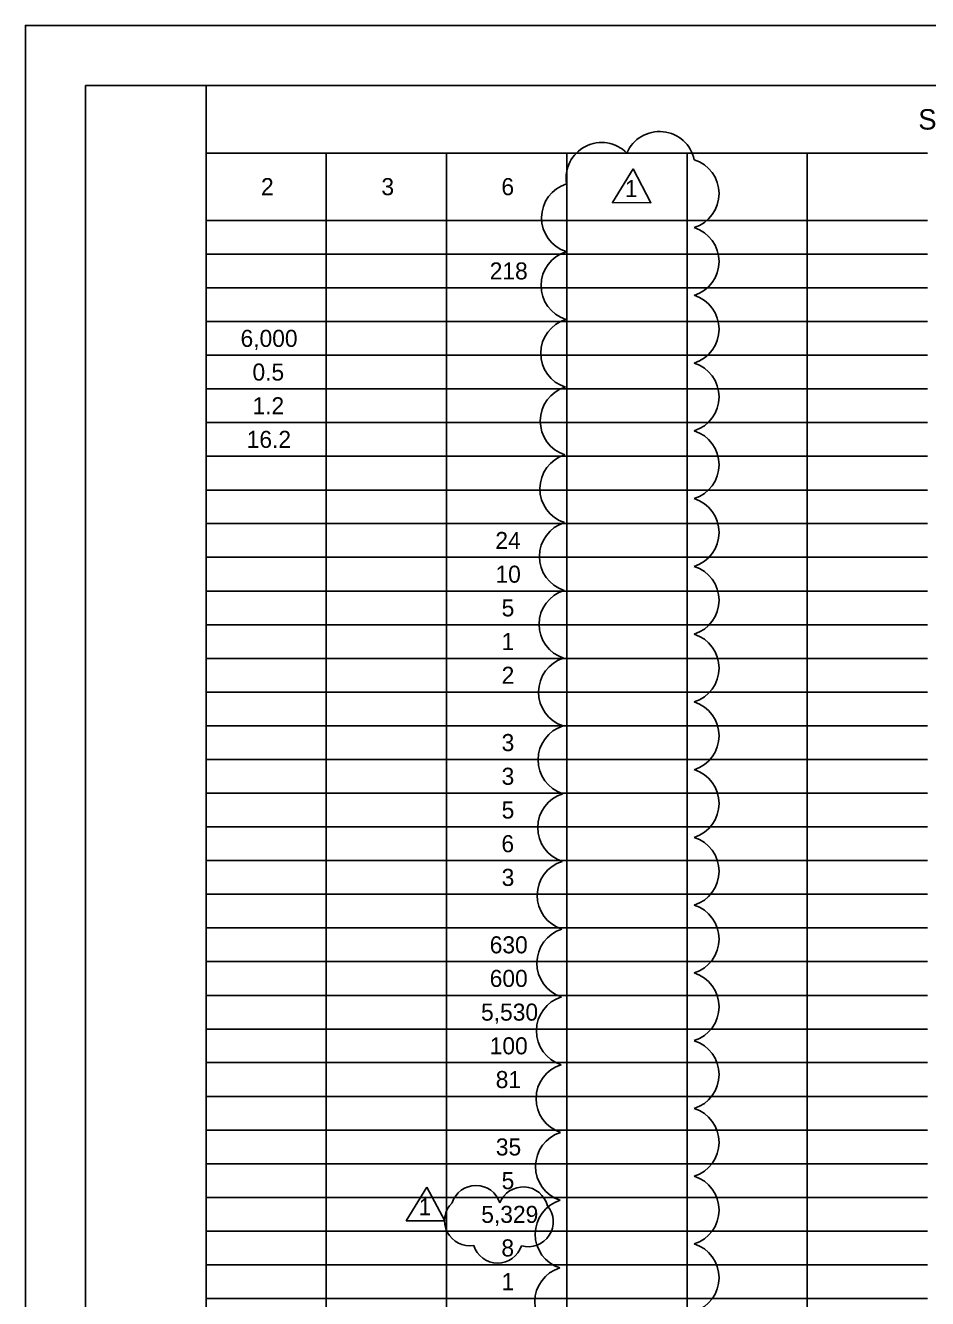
# Model space of a CAD drawing. Extents: x 0 to 34, y 0 to 22.
# Drawn here: x 0 to 7.49, y 11.42 to 22 of the extents above; entities that cross this region are included whole.
import ezdxf

# ---------------------------------------------------------------- set-up
doc = ezdxf.new("R2010")
doc.units = 0
for name, color, linetype in [('Default', 7, 'Continuous'), ('SH_Border', 7, 'Continuous'), ('SH_Cut_Line', 7, 'Continuous'), ('SH_Text', 7, 'Continuous')]:
    doc.layers.add(name, color=color, linetype=linetype)

msp = doc.modelspace()

# ---------------------------------------------------------------- linework, layer by layer
at = {"layer": 'Default'}
for points in [[(5.048, 20.808), (4.877, 20.529), (5.197, 20.527)], [(3.335, 12.35), (3.164, 12.071), (3.484, 12.069)]]:
    msp.add_lwpolyline(points, close=True, dxfattribs=at)
for centre, radius, start, end in [((5.268, 20.824), 0.295, 11.7951, 156.7951), ((4.787, 20.733), 0.295, 44.5745, 189.5745), ((5.468, 20.603), 0.295, 287.5295, 72.5295), ((4.583, 20.402), 0.295, 107.1401, 252.1401), ((5.468, 20.039), 0.295, 287.5, 72.5), ((4.579, 19.839), 0.295, 107.1401, 252.1401), ((5.468, 19.477), 0.295, 287.5, 72.5), ((4.576, 19.276), 0.295, 107.1401, 252.1401), ((5.468, 18.914), 0.295, 287.5, 72.5), ((4.572, 18.714), 0.295, 107.1401, 252.1401), ((5.468, 18.351), 0.295, 287.5, 72.5), ((4.569, 18.151), 0.295, 107.1401, 252.1401), ((5.468, 17.788), 0.295, 287.5, 72.5), ((4.565, 17.588), 0.295, 107.1401, 252.1401), ((5.468, 17.225), 0.295, 287.5, 72.5), ((4.562, 17.025), 0.295, 107.1401, 252.1401), ((5.468, 16.662), 0.295, 287.5, 72.5), ((4.558, 16.462), 0.295, 107.1401, 252.1401), ((5.468, 16.099), 0.295, 287.5, 72.5), ((4.554, 15.899), 0.295, 107.1401, 252.1401), ((5.468, 15.537), 0.295, 287.5, 72.5), ((4.551, 15.336), 0.295, 107.1401, 252.1401), ((5.468, 14.974), 0.295, 287.5, 72.5), ((4.547, 14.774), 0.295, 107.1401, 252.1401), ((5.468, 14.411), 0.295, 287.5, 72.5), ((4.544, 14.211), 0.295, 107.1401, 252.1401), ((5.468, 13.848), 0.295, 287.5, 72.5), ((4.54, 13.648), 0.295, 107.1401, 252.1401), ((5.468, 13.285), 0.295, 287.5, 72.5), ((4.537, 13.085), 0.295, 107.1401, 252.1401), ((5.468, 12.722), 0.295, 287.5, 72.5), ((4.533, 12.522), 0.295, 107.1401, 252.1401), ((5.468, 12.159), 0.295, 287.5, 72.5), ((3.743, 12.156), 0.208, 17.5, 162.5), ((4.135, 12.144), 0.208, 14.1039, 159.1039), ((3.69, 12.071), 0.208, 134.5743, 279.5743), ((4.177, 12.063), 0.208, 254.4905, 39.4905), ((4.53, 11.959), 0.295, 107.1401, 252.1401), ((3.923, 11.927), 0.208, 197.0681, 342.0681), ((5.468, 11.597), 0.295, 287.5, 72.5), ((4.526, 11.397), 0.295, 107.1401, 252.1401)]:
    msp.add_arc(centre, radius, start, end, dxfattribs=at)
at = {"layer": 'SH_Border'}
for points in [[(0.5, 21.5), (1.5, 21.5), (1.5, 0.5), (0.5, 0.5)], [(1.5, 21.5), (33.5, 21.5), (33.5, 0.5), (1.5, 0.5)]]:
    msp.add_lwpolyline(points, close=True, dxfattribs=at)
at = {"layer": 'SH_Cut_Line'}
msp.add_lwpolyline([(0, 0), (34, 0), (34, 22), (0, 22)], close=True, dxfattribs=at)
at = {"layer": 'SH_Text'}
for p, q in [((1.5, 21.5), (2.499, 21.5)), ((1.5, 21.5), (1.5, 21.22)), ((2.499, 21.5), (4.497, 21.5)), ((4.497, 21.5), (5.497, 21.5)), ((5.497, 21.5), (6.496, 21.5)), ((6.496, 21.5), (7.495, 21.5)), ((1.5, 21.22), (1.5, 20.94)), ((1.5, 20.94), (2.499, 20.94)), ((1.5, 20.94), (1.5, 20.66)), ((2.499, 20.94), (4.497, 20.94)), ((2.499, 20.94), (2.499, 20.66)), ((3.498, 20.94), (3.498, 20.66)), ((4.497, 20.94), (5.497, 20.94)), ((4.497, 20.94), (4.497, 20.66)), ((5.497, 20.94), (6.496, 20.94)), ((5.497, 20.94), (5.497, 20.66)), ((6.496, 20.94), (7.495, 20.94)), ((6.496, 20.94), (6.496, 20.66)), ((1.5, 20.66), (1.5, 20.38)), ((2.499, 20.66), (2.499, 20.38)), ((3.498, 20.66), (3.498, 20.38)), ((4.497, 20.66), (4.497, 20.38)), ((5.497, 20.66), (5.497, 20.38)), ((6.496, 20.66), (6.496, 20.38)), ((1.5, 20.38), (2.499, 20.38)), ((1.5, 20.38), (1.5, 20.101)), ((2.499, 20.38), (4.497, 20.38)), ((2.499, 20.38), (2.499, 20.101)), ((3.498, 20.38), (3.498, 20.101)), ((4.497, 20.38), (5.497, 20.38)), ((4.497, 20.38), (4.497, 20.101)), ((5.497, 20.38), (6.496, 20.38)), ((5.497, 20.38), (5.497, 20.101)), ((6.496, 20.38), (7.495, 20.38)), ((6.496, 20.38), (6.496, 20.101)), ((1.5, 20.101), (2.499, 20.101)), ((1.5, 20.101), (1.5, 18.701)), ((2.499, 20.101), (4.497, 20.101)), ((2.499, 20.101), (2.499, 18.701)), ((3.498, 20.101), (3.498, 18.701)), ((4.497, 20.101), (5.497, 20.101)), ((4.497, 20.101), (4.497, 18.701)), ((5.497, 20.101), (6.496, 20.101)), ((5.497, 20.101), (5.497, 18.701)), ((6.496, 20.101), (7.495, 20.101)), ((6.496, 20.101), (6.496, 18.701)), ((1.5, 19.821), (2.499, 19.821)), ((2.499, 19.821), (4.497, 19.821)), ((4.497, 19.821), (5.497, 19.821)), ((5.497, 19.821), (6.496, 19.821)), ((6.496, 19.821), (7.495, 19.821)), ((1.5, 19.541), (2.499, 19.541)), ((2.499, 19.541), (4.497, 19.541)), ((4.497, 19.541), (5.497, 19.541)), ((5.497, 19.541), (6.496, 19.541)), ((6.496, 19.541), (7.495, 19.541)), ((1.5, 19.261), (2.499, 19.261)), ((2.499, 19.261), (4.497, 19.261)), ((4.497, 19.261), (5.497, 19.261)), ((5.497, 19.261), (6.496, 19.261)), ((6.496, 19.261), (7.495, 19.261)), ((1.5, 18.981), (2.499, 18.981)), ((2.499, 18.981), (4.497, 18.981)), ((4.497, 18.981), (5.497, 18.981)), ((5.497, 18.981), (6.496, 18.981)), ((6.496, 18.981), (7.495, 18.981)), ((1.5, 18.701), (2.499, 18.701)), ((1.5, 18.701), (1.5, 18.141)), ((2.499, 18.701), (4.497, 18.701)), ((2.499, 18.701), (2.499, 18.141)), ((3.498, 18.701), (3.498, 18.141)), ((4.497, 18.701), (5.497, 18.701)), ((4.497, 18.701), (4.497, 18.141)), ((5.497, 18.701), (6.496, 18.701)), ((5.497, 18.701), (5.497, 18.141)), ((6.496, 18.701), (7.495, 18.701)), ((6.496, 18.701), (6.496, 18.141)), ((1.5, 18.421), (2.499, 18.421)), ((2.499, 18.421), (4.497, 18.421)), ((4.497, 18.421), (5.497, 18.421)), ((5.497, 18.421), (6.496, 18.421)), ((6.496, 18.421), (7.495, 18.421)), ((1.5, 18.141), (2.499, 18.141)), ((1.5, 18.141), (1.5, 17.862)), ((2.499, 18.141), (4.497, 18.141)), ((2.499, 18.141), (2.499, 17.862)), ((3.498, 18.141), (3.498, 17.862)), ((4.497, 18.141), (5.497, 18.141)), ((4.497, 18.141), (4.497, 17.862)), ((5.497, 18.141), (6.496, 18.141)), ((5.497, 18.141), (5.497, 17.862)), ((6.496, 18.141), (7.495, 18.141)), ((6.496, 18.141), (6.496, 17.862)), ((1.5, 17.862), (2.499, 17.862)), ((1.5, 17.862), (1.5, 17.582)), ((2.499, 17.862), (4.497, 17.862)), ((2.499, 17.862), (2.499, 17.582)), ((3.498, 17.862), (3.498, 17.582)), ((4.497, 17.862), (5.497, 17.862)), ((4.497, 17.862), (4.497, 17.582)), ((5.497, 17.862), (6.496, 17.862)), ((5.497, 17.862), (5.497, 17.582)), ((6.496, 17.862), (7.495, 17.862)), ((6.496, 17.862), (6.496, 17.582)), ((1.5, 17.582), (2.499, 17.582)), ((1.5, 17.582), (1.5, 17.302)), ((2.499, 17.582), (4.497, 17.582)), ((2.499, 17.582), (2.499, 17.302)), ((3.498, 17.582), (3.498, 17.302)), ((4.497, 17.582), (5.497, 17.582)), ((4.497, 17.582), (4.497, 17.302)), ((5.497, 17.582), (6.496, 17.582)), ((5.497, 17.582), (5.497, 17.302)), ((6.496, 17.582), (7.495, 17.582)), ((6.496, 17.582), (6.496, 17.302)), ((1.5, 17.302), (2.499, 17.302)), ((1.5, 17.302), (1.5, 17.022)), ((2.499, 17.302), (4.497, 17.302)), ((2.499, 17.302), (2.499, 17.022)), ((3.498, 17.302), (3.498, 17.022)), ((4.497, 17.302), (5.497, 17.302)), ((4.497, 17.302), (4.497, 17.022)), ((5.497, 17.302), (6.496, 17.302)), ((5.497, 17.302), (5.497, 17.022)), ((6.496, 17.302), (7.495, 17.302)), ((6.496, 17.302), (6.496, 17.022)), ((1.5, 17.022), (2.499, 17.022)), ((1.5, 17.022), (1.5, 16.742)), ((2.499, 17.022), (4.497, 17.022)), ((2.499, 17.022), (2.499, 16.742)), ((3.498, 17.022), (3.498, 16.742)), ((4.497, 17.022), (5.497, 17.022)), ((4.497, 17.022), (4.497, 16.742)), ((5.497, 17.022), (6.496, 17.022)), ((5.497, 17.022), (5.497, 16.742)), ((6.496, 17.022), (7.495, 17.022)), ((6.496, 17.022), (6.496, 16.742)), ((1.5, 16.742), (2.499, 16.742)), ((1.5, 16.742), (1.5, 16.182)), ((2.499, 16.742), (4.497, 16.742)), ((2.499, 16.742), (2.499, 16.182)), ((3.498, 16.742), (3.498, 16.182)), ((4.497, 16.742), (5.497, 16.742)), ((4.497, 16.742), (4.497, 16.182)), ((5.497, 16.742), (6.496, 16.742)), ((5.497, 16.742), (5.497, 16.182)), ((6.496, 16.742), (7.495, 16.742)), ((6.496, 16.742), (6.496, 16.182)), ((1.5, 16.462), (2.499, 16.462)), ((2.499, 16.462), (4.497, 16.462)), ((4.497, 16.462), (5.497, 16.462)), ((5.497, 16.462), (6.496, 16.462)), ((6.496, 16.462), (7.495, 16.462)), ((1.5, 16.182), (2.499, 16.182)), ((1.5, 16.182), (1.5, 15.902)), ((2.499, 16.182), (4.497, 16.182)), ((2.499, 16.182), (2.499, 15.902)), ((3.498, 16.182), (3.498, 15.902)), ((4.497, 16.182), (5.497, 16.182)), ((4.497, 16.182), (4.497, 15.902)), ((5.497, 16.182), (6.496, 16.182)), ((5.497, 16.182), (5.497, 15.902)), ((6.496, 16.182), (7.495, 16.182)), ((6.496, 16.182), (6.496, 15.902)), ((1.5, 15.902), (2.499, 15.902)), ((1.5, 15.902), (1.5, 15.623)), ((2.499, 15.902), (4.497, 15.902)), ((2.499, 15.902), (2.499, 15.623)), ((3.498, 15.902), (3.498, 15.623)), ((4.497, 15.902), (5.497, 15.902)), ((4.497, 15.902), (4.497, 15.623)), ((5.497, 15.902), (6.496, 15.902)), ((5.497, 15.902), (5.497, 15.623)), ((6.496, 15.902), (7.495, 15.902)), ((6.496, 15.902), (6.496, 15.623)), ((1.5, 15.623), (2.499, 15.623)), ((1.5, 15.623), (1.5, 15.343)), ((2.499, 15.623), (4.497, 15.623)), ((2.499, 15.623), (2.499, 15.343)), ((3.498, 15.623), (3.498, 15.343)), ((4.497, 15.623), (5.497, 15.623)), ((4.497, 15.623), (4.497, 15.343)), ((5.497, 15.623), (6.496, 15.623)), ((5.497, 15.623), (5.497, 15.343)), ((6.496, 15.623), (7.495, 15.623)), ((6.496, 15.623), (6.496, 15.343)), ((1.5, 15.343), (2.499, 15.343)), ((1.5, 15.343), (1.5, 14.783)), ((2.499, 15.343), (4.497, 15.343)), ((2.499, 15.343), (2.499, 14.783)), ((3.498, 15.343), (3.498, 14.783)), ((4.497, 15.343), (5.497, 15.343)), ((4.497, 15.343), (4.497, 14.783)), ((5.497, 15.343), (6.496, 15.343)), ((5.497, 15.343), (5.497, 14.783)), ((6.496, 15.343), (7.495, 15.343)), ((6.496, 15.343), (6.496, 14.783)), ((1.5, 15.063), (2.499, 15.063)), ((2.499, 15.063), (4.497, 15.063)), ((4.497, 15.063), (5.497, 15.063)), ((5.497, 15.063), (6.496, 15.063)), ((6.496, 15.063), (7.495, 15.063)), ((1.5, 14.783), (2.499, 14.783)), ((1.5, 14.783), (1.5, 14.503)), ((2.499, 14.783), (4.497, 14.783)), ((2.499, 14.783), (2.499, 14.503)), ((3.498, 14.783), (3.498, 14.503)), ((4.497, 14.783), (5.497, 14.783)), ((4.497, 14.783), (4.497, 14.503)), ((5.497, 14.783), (6.496, 14.783)), ((5.497, 14.783), (5.497, 14.503)), ((6.496, 14.783), (7.495, 14.783)), ((6.496, 14.783), (6.496, 14.503)), ((1.5, 14.503), (2.499, 14.503)), ((1.5, 14.503), (1.5, 14.223)), ((2.499, 14.503), (4.497, 14.503)), ((2.499, 14.503), (2.499, 14.223)), ((3.498, 14.503), (3.498, 14.223)), ((4.497, 14.503), (5.497, 14.503)), ((4.497, 14.503), (4.497, 14.223)), ((5.497, 14.503), (6.496, 14.503)), ((5.497, 14.503), (5.497, 14.223)), ((6.496, 14.503), (7.495, 14.503)), ((6.496, 14.503), (6.496, 14.223)), ((1.5, 14.223), (2.499, 14.223)), ((1.5, 14.223), (1.5, 13.943)), ((2.499, 14.223), (4.497, 14.223)), ((2.499, 14.223), (2.499, 13.943)), ((3.498, 14.223), (3.498, 13.943)), ((4.497, 14.223), (5.497, 14.223)), ((4.497, 14.223), (4.497, 13.943)), ((5.497, 14.223), (6.496, 14.223)), ((5.497, 14.223), (5.497, 13.943)), ((6.496, 14.223), (7.495, 14.223)), ((6.496, 14.223), (6.496, 13.943)), ((1.5, 13.943), (2.499, 13.943)), ((1.5, 13.943), (1.5, 11.704)), ((2.499, 13.943), (4.497, 13.943)), ((2.499, 13.943), (2.499, 11.704)), ((3.498, 13.943), (3.498, 11.704)), ((4.497, 13.943), (5.497, 13.943)), ((4.497, 13.943), (4.497, 11.704)), ((5.497, 13.943), (6.496, 13.943)), ((5.497, 13.943), (5.497, 11.704)), ((6.496, 13.943), (7.495, 13.943)), ((6.496, 13.943), (6.496, 11.704)), ((1.5, 13.663), (2.499, 13.663)), ((2.499, 13.663), (4.497, 13.663)), ((4.497, 13.663), (5.497, 13.663)), ((5.497, 13.663), (6.496, 13.663)), ((6.496, 13.663), (7.495, 13.663)), ((1.5, 13.384), (2.499, 13.384)), ((2.499, 13.384), (4.497, 13.384)), ((4.497, 13.384), (5.497, 13.384)), ((5.497, 13.384), (6.496, 13.384)), ((6.496, 13.384), (7.495, 13.384)), ((1.5, 13.104), (2.499, 13.104)), ((2.499, 13.104), (4.497, 13.104)), ((4.497, 13.104), (5.497, 13.104)), ((5.497, 13.104), (6.496, 13.104)), ((6.496, 13.104), (7.495, 13.104)), ((1.5, 12.824), (2.499, 12.824)), ((2.499, 12.824), (4.497, 12.824)), ((4.497, 12.824), (5.497, 12.824)), ((5.497, 12.824), (6.496, 12.824)), ((6.496, 12.824), (7.495, 12.824)), ((1.5, 12.544), (2.499, 12.544)), ((2.499, 12.544), (4.497, 12.544)), ((4.497, 12.544), (5.497, 12.544)), ((5.497, 12.544), (6.496, 12.544)), ((6.496, 12.544), (7.495, 12.544)), ((1.5, 12.264), (2.499, 12.264)), ((2.499, 12.264), (4.497, 12.264)), ((4.497, 12.264), (5.497, 12.264)), ((5.497, 12.264), (6.496, 12.264)), ((6.496, 12.264), (7.495, 12.264)), ((1.5, 11.984), (2.499, 11.984)), ((2.499, 11.984), (4.497, 11.984)), ((4.497, 11.984), (5.497, 11.984)), ((5.497, 11.984), (6.496, 11.984)), ((6.496, 11.984), (7.495, 11.984)), ((1.5, 11.704), (2.499, 11.704)), ((1.5, 11.704), (1.5, 11.424)), ((2.499, 11.704), (4.497, 11.704)), ((2.499, 11.704), (2.499, 11.424)), ((3.498, 11.704), (3.498, 11.424)), ((4.497, 11.704), (5.497, 11.704)), ((4.497, 11.704), (4.497, 11.424)), ((5.497, 11.704), (6.496, 11.704)), ((5.497, 11.704), (5.497, 11.424)), ((6.496, 11.704), (7.495, 11.704)), ((6.496, 11.704), (6.496, 11.424)), ((1.5, 11.424), (2.499, 11.424)), ((1.5, 11.424), (1.5, 10.305)), ((2.499, 11.424), (4.497, 11.424)), ((2.499, 11.424), (2.499, 10.305)), ((3.498, 11.424), (3.498, 10.305)), ((4.497, 11.424), (5.497, 11.424)), ((4.497, 11.424), (4.497, 10.305)), ((5.497, 11.424), (6.496, 11.424)), ((5.497, 11.424), (5.497, 10.305)), ((6.496, 11.424), (7.495, 11.424)), ((6.496, 11.424), (6.496, 10.305))]:
    msp.add_line(p, q, dxfattribs=at)

# ---------------------------------------------------------------- texts
at = {"layer": 'Default'}
for p in [(4.98, 20.575), (3.267, 12.117)]:
    msp.add_text('1', height=0.14, dxfattribs=at).set_placement(p)
at = {"layer": 'SH_Text'}
for s, height, p in [('SHEET NUM.', 0.1699, (7.418, 21.135)), ('2', 0.142, (1.957, 20.59)), ('3', 0.142, (2.957, 20.59)), ('6', 0.142, (3.954, 20.59)), ('218', 0.1416, (3.857, 19.89)), ('6,000', 0.1416, (1.787, 19.33)), ('0.5', 0.1416, (1.886, 19.05)), ('1.2', 0.1416, (1.886, 18.77)), ('16.2', 0.1416, (1.838, 18.491)), ('24', 0.1416, (3.904, 17.651)), ('10', 0.1416, (3.905, 17.371)), ('5', 0.142, (3.956, 17.091)), ('1', 0.142, (3.955, 16.811)), ('2', 0.142, (3.956, 16.531)), ('3', 0.142, (3.956, 15.972)), ('3', 0.142, (3.956, 15.692)), ('5', 0.142, (3.956, 15.412)), ('6', 0.142, (3.954, 15.132)), ('3', 0.142, (3.956, 14.852)), ('630', 0.1416, (3.857, 14.292)), ('600', 0.1416, (3.857, 14.013)), ('5,530', 0.1416, (3.785, 13.733)), ('100', 0.1416, (3.857, 13.453)), ('81', 0.1416, (3.907, 13.173)), ('35', 0.1416, (3.908, 12.613)), ('5', 0.142, (3.956, 12.333)), ('5,329', 0.1416, (3.787, 12.053)), ('8', 0.142, (3.954, 11.774)), ('1', 0.142, (3.955, 11.494))]:
    msp.add_text(s, height=height, dxfattribs=at).set_placement(p)

doc.saveas('drawing.dxf')
